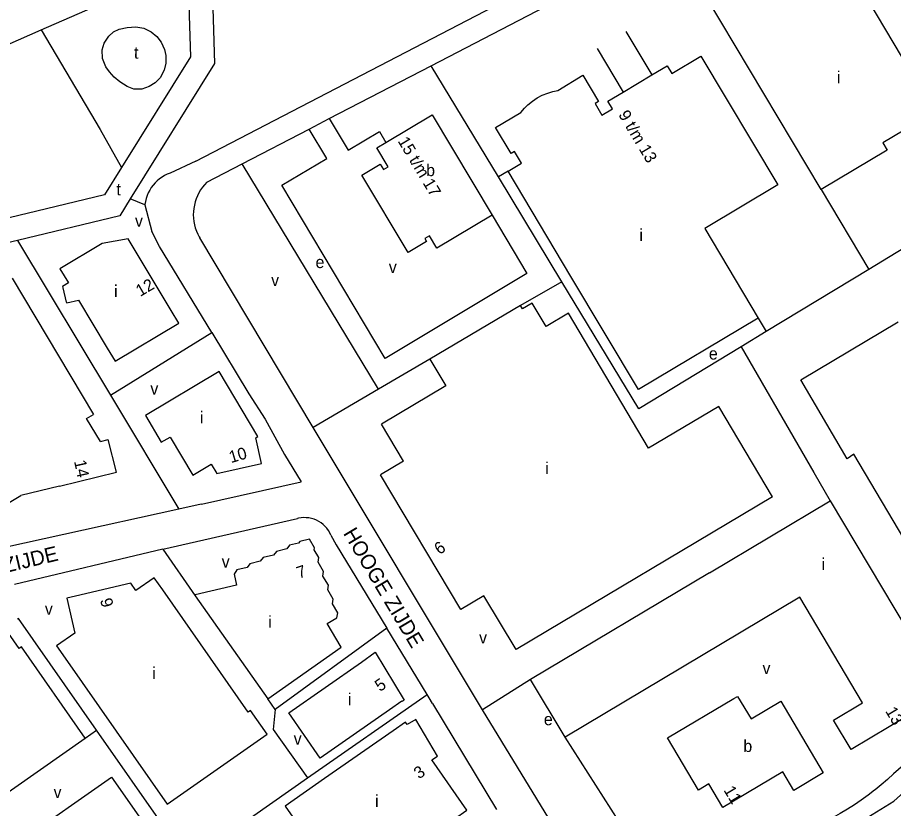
# Model space of a CAD drawing. Extents: x 156721 to 158827, y 386657 to 388950.
# Drawn here: x 157336.1 to 157630, y 388308.9 to 388574.1 of the extents above; entities that cross this region are included whole.
import ezdxf

# ---------------------------------------------------------------- set-up
doc = ezdxf.new("R2010")
doc.units = 0
for name, color, linetype in [('BLT_Basislijn', 7, 'Continuous'), ('BLT_Bebouwing', 7, 'Continuous'), ('BLT_Centroide', 7, 'Continuous'), ('BLT_Huisnummer', 7, 'Continuous'), ('BLT_Huisnummer_reeks', 7, 'Continuous'), ('BLT_Straatnaam', 7, 'Continuous')]:
    doc.layers.add(name, color=color, linetype=linetype)

msp = doc.modelspace()

# ---------------------------------------------------------------- linework, layer by layer
at = {"layer": 'BLT_Basislijn'}
for p, q in [((157395.93, 388525.94), (157642.53, 388654)), ((157474.89, 388557.93), (157555.72, 388599.91)), ((157540.24, 388569.45), (157548.97, 388554.85)), ((157530.62, 388563.73), (157539.36, 388549.1)), ((157440.72, 388540.19), (157474.89, 388557.93)), ((157497.47, 388520.64), (157474.89, 388557.93)), ((157433.97, 388536.68), (157440.72, 388540.19)), ((157411.48, 388525), (157433.97, 388536.68)), ((157395.93, 388525.94), (157387.3, 388521.89)), ((157399.62, 388518.84), (157411.48, 388525)), ((157457.24, 388449.43), (157411.48, 388525)), ((157500.72, 388522.58), (157497.47, 388520.64)), ((157518.74, 388485.51), (157497.47, 388520.64)), ((157605.78, 388516.39), (157621.78, 388489.64)), ((157378.87, 388511.31), (157373.95, 388513.29)), ((157378.87, 388511.31), (157381.22, 388502.39)), ((157336.15, 388499.37), (157315.55, 388494.43)), ((157336.15, 388499.37), (157367.32, 388447.43)), ((157435.35, 388436.63), (157397.23, 388500.22)), ((157518.74, 388485.51), (157504.85, 388477.51)), ((157584.66, 388473.32), (157587.36, 388468.8)), ((157372.53, 388450.66), (157401.26, 388468.46)), ((157578.94, 388463.7), (157603.3, 388421.48)), ((157474.48, 388459.51), (157457.24, 388449.43)), ((157367.32, 388447.43), (157372.53, 388450.66)), ((157457.24, 388449.43), (157435.35, 388436.63)), ((157367.32, 388447.43), (157390.22, 388409.26)), ((157603.3, 388421.48), (157608.76, 388412.02)), ((157397.86, 388410.93), (157431.26, 388418.35)), ((157397.86, 388410.93), (157396.78, 388410.7)), ((157396.78, 388410.7), (157390.22, 388409.26)), ((157384.91, 388395.79), (157430.04, 388406.12)), ((157384.91, 388395.79), (157335.1, 388383.94)), ((157384.91, 388395.79), (157395.77, 388380.18)), ((157568.32, 388387.89), (157508.27, 388352.08)), ((157459.99, 388369.27), (157422.58, 388342.09)), ((157473.55, 388347.03), (157459.99, 388369.27)), ((157508.27, 388352.08), (157492.16, 388341.94)), ((157433.45, 388319.09), (157473.55, 388347.03)), ((157422.58, 388342.09), (157420.06, 388345.61)), ((157475.33, 388344.1), (157496.79, 388308.52)), ((157651.82, 388339.54), (157630.02, 388320.43)), ((157358.82, 388332.44), (157362.65, 388335.12)), ((157393.36, 388291.17), (157362.65, 388335.12)), ((157400.35, 388296.04), (157433.45, 388319.09))]:
    msp.add_line(p, q, dxfattribs=at)
for points in [[(157344.1, 388569.94), (157393.93, 388591.74)], [(157393.29, 388588.85), (157394.14, 388560.88), (157371.05, 388523.77)], [(157401.37, 388584.79), (157402.21, 388558.71), (157373.95, 388513.29)], [(157277.17, 388537.82), (157306.89, 388553.66), (157344.1, 388569.94)], [(157344.1, 388569.94), (157363.88, 388536.54), (157371.05, 388523.77)], [(157440.72, 388540.19), (157447.06, 388529.57), (157457.55, 388535.83), (157459.71, 388532.22)], [(157495.39, 388507.77), (157507.06, 388488.25), (157459.45, 388459.81), (157424.79, 388517.84), (157439.85, 388526.84), (157433.97, 388536.68)], [(157371.05, 388523.77), (157365.34, 388514.6), (157313.68, 388502.21)], [(157387.3, 388521.89), (157386.36, 388521.52), (157385.46, 388521.07), (157384.59, 388520.56), (157383.76, 388519.98), (157382.99, 388519.33), (157382.27, 388518.62), (157381.6, 388517.86), (157381, 388517.05), (157380.47, 388516.2), (157380, 388515.3), (157379.61, 388514.38), (157379.29, 388513.42), (157379.05, 388512.44), (157378.88, 388511.44), (157378.87, 388511.31)], [(157399.62, 388518.84), (157398.86, 388518.04), (157398.17, 388517.18), (157397.53, 388516.27), (157396.97, 388515.32), (157396.48, 388514.33), (157396.05, 388513.31), (157395.71, 388512.26), (157395.44, 388511.19), (157395.25, 388510.1), (157395.14, 388509), (157395.1, 388507.9), (157395.15, 388506.79), (157395.28, 388505.69), (157395.48, 388504.61), (157395.77, 388503.54), (157396.13, 388502.49), (157396.57, 388501.48), (157397.07, 388500.5), (157397.23, 388500.22)], [(157373.95, 388513.29), (157370.4, 388507.58), (157336.15, 388499.37)], [(157401.26, 388468.46), (157383.7, 388497.26), (157381.22, 388502.39)], [(157638.1, 388499.53), (157621.78, 388489.64)], [(157621.78, 388489.64), (157587.36, 388468.8)], [(157556.21, 388449.94), (157544.56, 388442.88), (157518.74, 388485.51)], [(157401.26, 388468.46), (157413.7, 388447.86), (157419.19, 388439.36), (157425.72, 388427.52), (157431.26, 388418.35)], [(157587.36, 388468.8), (157578.94, 388463.7)], [(157578.94, 388463.7), (157556.21, 388449.94)], [(157492.16, 388341.94), (157435.35, 388436.63)], [(157390.22, 388409.26), (157312.96, 388392.29)], [(157441.28, 388400.55), (157440.89, 388401.34), (157440.42, 388402.1), (157439.89, 388402.81), (157439.3, 388403.47), (157438.65, 388404.07), (157437.95, 388404.61), (157437.21, 388405.09), (157436.42, 388405.49), (157435.6, 388405.83), (157434.75, 388406.08), (157433.89, 388406.27), (157433.01, 388406.37), (157432.12, 388406.39), (157431.24, 388406.33), (157430.36, 388406.2), (157430.04, 388406.12)], [(157441.28, 388400.55), (157443.05, 388397.29), (157459.99, 388369.27)], [(157362.65, 388335.12), (157336.48, 388372.58), (157336.07, 388372.3)], [(157475.33, 388344.1), (157474.22, 388345.93), (157473.55, 388347.03)], [(157552.85, 388284.58), (157562.27, 388288.83), (157576.98, 388292.83), (157591.14, 388294.71), (157604.51, 388297.91), (157617.07, 388303.26), (157630.17, 388311.28), (157641.66, 388321.7), (157668.88, 388347.46)], [(157422.58, 388342.09), (157421.9, 388335.38), (157433.45, 388319.09)], [(157528.54, 388282.21), (157492.16, 388341.94)], [(157548.16, 388288.54), (157519.84, 388332.72)], [(157630.02, 388320.43), (157627.97, 388318.56), (157625.86, 388316.74), (157623.89, 388315.15)], [(157623.89, 388315.15), (157623.7, 388314.99), (157621.49, 388313.3), (157619.23, 388311.68), (157616.93, 388310.12), (157614.58, 388308.63), (157612.19, 388307.21), (157609.76, 388305.85), (157607.3, 388304.57), (157604.79, 388303.36), (157604.06, 388303.02)]]:
    msp.add_lwpolyline(points, dxfattribs=at)
msp.add_lwpolyline([(157365.72, 388557.58), (157364.64, 388560.36), (157364.56, 388563.29), (157365.2, 388565.52), (157366.73, 388567.88), (157368.37, 388569.28), (157370.2, 388570.19), (157372.87, 388570.79), (157375.83, 388571.02), (157378.46, 388570.52), (157380.95, 388569.34), (157382.87, 388567.76), (157384.33, 388565.86), (157385.41, 388563.42), (157385.82, 388561.32), (157385.88, 388558.83), (157385.33, 388556.4), (157383.97, 388553.91), (157382.32, 388552.19), (157380.32, 388550.92), (157377.78, 388550.12), (157375.17, 388550.04), (157372.89, 388551.02), (157370.46, 388552.52), (157368.59, 388554.08), (157366.96, 388555.86)], close=True, dxfattribs=at)
at = {"layer": 'BLT_Bebouwing'}
for p, q in [((157605.78, 388516.39), (157564.84, 388584.96)), ((157334.32, 388486.67), (157361.58, 388441.01)), ((157504.85, 388477.51), (157474.48, 388459.51)), ((157589.42, 388413.33), (157571.44, 388443.66)), ((157359.3, 388439.65), (157361.58, 388441.01)), ((157363.91, 388431.97), (157359.3, 388439.65)), ((157465.64, 388425.38), (157458.28, 388437.73)), ((157363.91, 388431.97), (157366.58, 388432.62)), ((157369.27, 388421.64), (157366.58, 388432.62)), ((157465.64, 388425.38), (157457.93, 388420.76)), ((157484.84, 388375.62), (157457.93, 388420.76)), ((157350.19, 388416.92), (157337.25, 388413.76)), ((157589.42, 388413.33), (157503.38, 388362.22)), ((157395.77, 388380.18), (157420.06, 388345.61)), ((157492.6, 388380.22), (157484.84, 388375.62)), ((157503.38, 388362.22), (157492.6, 388380.22)), ((157439.15, 388318.87), (157425.93, 388309.64))]:
    msp.add_line(p, q, dxfattribs=at)
for points in [[(157617.92, 388606.99), (157631.09, 388584.92), (157632.51, 388582.55), (157627.01, 388579.27), (157625.55, 388581.71), (157621.73, 388579.33), (157643.79, 388542.4), (157626.43, 388532.05), (157627.89, 388529.61), (157605.78, 388516.39)], [(157548.97, 388554.85), (157554.09, 388557.91), (157555.65, 388555.38), (157565.37, 388561.17)], [(157565.37, 388561.17), (157591.19, 388517.97), (157566.74, 388503.36), (157584.66, 388473.32)], [(157502.47, 388523.62), (157505.19, 388525.25), (157502.88, 388529.14), (157501.71, 388528.47), (157496.47, 388537.2), (157504.98, 388542.26), (157506.17, 388543.66), (157507.36, 388544.82), (157508.88, 388546.06), (157510.48, 388547.12), (157512.15, 388548.02), (157514, 388548.78), (157515.72, 388549.32), (157517.36, 388549.67), (157525.85, 388554.75), (157531.07, 388545.98), (157529.89, 388545.26), (157532.2, 388541.4), (157535.77, 388543.53), (157534.23, 388546.03), (157539.36, 388549.1)], [(157539.36, 388549.1), (157548.97, 388554.85)], [(157459.71, 388532.22), (157475.25, 388541.49), (157495.39, 388507.77)], [(157495.39, 388507.77), (157476.76, 388496.75), (157474.3, 388500.87), (157472.76, 388499.95), (157473.34, 388498.98), (157467.15, 388495.29), (157451.62, 388521.29), (157457.8, 388524.98), (157458.91, 388523.13), (157460.45, 388524.05), (157456.66, 388530.39), (157459.71, 388532.22)], [(157500.72, 388522.58), (157502.47, 388523.62)], [(157521.79, 388487.3), (157500.72, 388522.58)], [(157366.22, 388463.23), (157368.84, 388458.85), (157390.21, 388471.58), (157387.65, 388475.87), (157373.29, 388499.94), (157364.54, 388498.33), (157350.34, 388489.82)], [(157350.34, 388489.82), (157353.18, 388485.09), (157351.24, 388483.89), (157351.33, 388483.5), (157352.44, 388478.63), (157352.58, 388478.68), (157352.69, 388478.47), (157356.59, 388479.35), (157366.22, 388463.23)], [(157584.66, 388473.32), (157544.46, 388449.32), (157521.79, 388487.3)], [(157571.44, 388443.66), (157547.87, 388429.69), (157521.03, 388474.96), (157513.44, 388470.46), (157508.77, 388478.34), (157505.51, 388476.4), (157504.85, 388477.51)], [(157650.6, 388370.54), (157616.7, 388427.68), (157614.49, 388426.12), (157598.9, 388452.58), (157631.64, 388472.01)], [(157474.48, 388459.51), (157479.83, 388450.59), (157458.28, 388437.73)], [(157403.76, 388455.37), (157379.01, 388440.62), (157384.33, 388431.65), (157387.34, 388433.43), (157394.95, 388420.61), (157401.1, 388424.27), (157402.96, 388421.16), (157418.01, 388424.58), (157416.06, 388433.18), (157416.73, 388433.58), (157403.76, 388455.37)], [(157350.19, 388416.92), (157369.27, 388421.64)], [(157326.17, 388407.17), (157337.25, 388413.76)], [(157568.32, 388387.89), (157608.76, 388412.02)], [(157608.76, 388412.02), (157643.55, 388353.78)], [(157420.06, 388345.61), (157444.7, 388362.93), (157439.97, 388370.87), (157443.2, 388372.79), (157443.63, 388374.43), (157441.79, 388377.51), (157442.04, 388379.07), (157440.2, 388382.14), (157440.44, 388383.69), (157438.59, 388386.78), (157438.82, 388388.33), (157436.98, 388391.42), (157437.24, 388392.97), (157435.63, 388395.61), (157435.8, 388396.3), (157434.06, 388399.15), (157430.8, 388398.41), (157430.41, 388397.83), (157427.4, 388397.15), (157426.44, 388395.89), (157422.97, 388395.07), (157422.01, 388393.81), (157418.54, 388392.98), (157417.56, 388391.74), (157414.09, 388390.89), (157413.13, 388389.67), (157409.66, 388388.86), (157408.75, 388387.38), (157409.61, 388383.72), (157395.72, 388380.45), (157395.77, 388380.18)], [(157413.48, 388341.19), (157384.84, 388382.15), (157381.98, 388386.25), (157375.84, 388381.96), (157374.12, 388384.43), (157355.55, 388380.06), (157352.62, 388379.37), (157355.35, 388367.64), (157349.21, 388363.35)], [(157615.8, 388328.62), (157609.9, 388338.49), (157619.66, 388344.34), (157598.56, 388379.69), (157519.84, 388332.72)], [(157358.82, 388332.44), (157337.44, 388363.03), (157336.71, 388362.51), (157333.09, 388367.67), (157327.46, 388364.16)], [(157349.21, 388363.35), (157352.07, 388359.26), (157386.29, 388310.31)], [(157460.98, 388341.98), (157437.68, 388325.76), (157427.11, 388340.94), (157451.48, 388357.89), (157456.16, 388361.27), (157465.79, 388345.19), (157465.17, 388344.76), (157465.08, 388344.84), (157460.98, 388341.98)], [(157519.84, 388332.72), (157508.27, 388352.08)], [(157643.55, 388353.78), (157637.34, 388350.08), (157641.29, 388343.79), (157615.8, 388328.62)], [(157572.74, 388309.2), (157568.08, 388317.09), (157564.66, 388315.05), (157554.22, 388332.52), (157576.45, 388345.71), (157577.69, 388346.46), (157582.28, 388338.89), (157592.18, 388344.8), (157606.49, 388320.82), (157596.61, 388314.92), (157592.85, 388321.19), (157572.74, 388309.2)], [(157386.29, 388310.31), (157419.87, 388333.79), (157414.3, 388341.76), (157413.48, 388341.19)], [(157425.93, 388309.64), (157446.49, 388280.09), (157482.75, 388305.38), (157486.85, 388308.24), (157475.11, 388325.14), (157477.04, 388326.43), (157469.71, 388338.68), (157466.83, 388336.98), (157466.26, 388337.78)], [(157466.26, 388337.78), (157462.16, 388334.92), (157439.15, 388318.87)], [(157327.6, 388310.61), (157358.82, 388332.44)], [(157336.63, 388297.68), (157367.7, 388319.4), (157389.36, 388288.41)]]:
    msp.add_lwpolyline(points, dxfattribs=at)

# ---------------------------------------------------------------- texts
at = {"layer": 'BLT_Centroide'}
for p in [(157375.15, 388560.33), (157369.28, 388514.5)]:
    msp.add_text('t', height=4, rotation=359, dxfattribs=at).set_placement(p)
for s, p in [('i', (157611.06, 388552.06)), ('b', (157473.22, 388520.91)), ('v', (157375.53, 388503.94)), ('i', (157544.78, 388499.2)), ('e', (157436.11, 388490.08)), ('v', (157460.7, 388488.44)), ('i', (157368.5, 388480.38)), ('v', (157421.21, 388484.07)), ('e', (157568.09, 388459.41)), ('v', (157380.69, 388447.68)), ('i', (157397.33, 388438)), ('i', (157513.15, 388420.99)), ('v', (157404.63, 388389.65)), ('i', (157605.94, 388388.83)), ('v', (157345.29, 388373.81)), ('i', (157420.22, 388369.45)), ('v', (157490.98, 388364.19)), ('i', (157381.34, 388352.27)), ('v', (157586.08, 388353.95)), ('i', (157446.99, 388343.5)), ('e', (157512.72, 388336.78)), ('v', (157428.78, 388330.27)), ('b', (157579.66, 388327.81)), ('v', (157348.21, 388312.37)), ('i', (157456.08, 388309.38))]:
    msp.add_text(s, height=4, dxfattribs=at).set_placement(p)
at = {"layer": 'BLT_Huisnummer'}
for s, rotation, p in [('12', 30.3903, (157377.27, 388480.38)), ('10', 16.3831, (157407.72, 388424.65)), ('14', 282.3833, (157355.05, 388425.3)), ('6', 34.8503, (157477.7, 388393.81)), ('7', 18.2603, (157430.52, 388385.89)), ('9', 285.0752, (157363.77, 388378.81)), ('5', 34.8503, (157457.75, 388347.88)), ('13', 300.9891, (157627.16, 388341.52)), ('3', 34.8958, (157470.83, 388318.57)), ('11', 300.9891, (157572.9, 388315.02))]:
    msp.add_text(s, height=4, rotation=rotation, dxfattribs=at).set_placement(p)
at = {"layer": 'BLT_Huisnummer_reeks'}
for s, rotation, p in [('9 t/m 13', 300.8775, (157537.6, 388541.54)), ('15 t/m 17', 300.8512, (157463.57, 388532.7))]:
    msp.add_text(s, height=4, rotation=rotation, dxfattribs=at).set_placement(p)
at = {"layer": 'BLT_Straatnaam'}
for rotation, p in [(300.843, (157445.23, 388401.14)), (13.3748, (157305.99, 388381.61))]:
    msp.add_text('HOOGE ZIJDE', height=5, rotation=rotation, dxfattribs=at).set_placement(p)

doc.saveas('drawing.dxf')
